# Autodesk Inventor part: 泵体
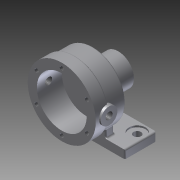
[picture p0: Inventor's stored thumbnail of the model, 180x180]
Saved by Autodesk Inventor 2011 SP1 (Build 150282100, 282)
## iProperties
Created: 2013-12
Part Number: 泵体
Document SubType Name: Modeling
Designer: Administrator
Density: 1 g/cm^3
Author: Administrator
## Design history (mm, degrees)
sketch "草图1"
  geometry: L1 (-48, 19)-(48, 19); L2 (48, 19)-(48, -19); L3 (48, -19)-(-48, -19); L4 (-48, -19)-(-48, 19); 3 further points
  constraints: 8 end point, 2 midpoint, 2 parallel, 1 horizontal, 1 horizontal alignment, 1 perpendicular, 1 vertical alignment
  dimensions: "d0" = 96 distance of L1.start L1.end; "d1" = 38 distance of L3.end L1.start
extrude "拉伸1" new body sketch "草图1" distance "d2" = 10; taper "d3" = 0 deg
node "工作平面1"
sketch "草图2"
  geometry: C1 r 41 at (48, 50); 1 further point
  constraints: 1 centre point
  dimensions: "d5" = 82 diameter of C1; "d6" = 50 distance of point (48, 0) C1.centre
extrude "拉伸2" join sketch "草图2" distance "d7" = 16; taper "d8" = 0 deg
sketch "草图3"
  geometry: C1 r 41 at (0, 0) reference; C2 r 39 at (0, 0); 1 further point
  constraints: 1 centre point, 1 coincident
  dimensions: "d9" = 78 diameter of C2
extrude "拉伸3" join sketch "草图3" distance "d10" = 22; taper "d11" = 0 deg
sketch "草图4"
  geometry: C1 r 39 at (0, 0) reference; C2 r 19 at (0, 0); 1 further point
  constraints: 1 centre point, 1 coincident
  dimensions: "d12" = 38 diameter of C2
extrude "拉伸4" join sketch "草图4" distance "d13" = 30; taper "d14" = 0 deg
sketch "草图5"
  geometry: L1 (48, -19)-(-48, -19) reference; L2 (-25, -19)-(25, -19); L3 (25, -19)-(25, -9); L4 (25, -9)-(-25, -9); L5 (-25, -9)-(-25, -19); 2 further points
  constraints: 8 end point, 2 midpoint, 2 parallel, 1 horizontal, 1 perpendicular
  dimensions: "d15" = 50 distance of L3.end L4.end; "d16" = 10 distance of L4.end L2.start
extrude "拉伸5" join sketch "草图5" stored distance "d17" = 40; taper "d18" = 0 deg
sketch "草图6"
  geometry: L1 (-9, 31)-(21, 31) reference; L2 (-19, 10)-(19, 10) reference; L3 (19, 10)-(14, 31); 1 further point
  constraints: 2 end point, 1 point on line
  dimensions: "d19" = 7 distance of L1.end L3.end
feature "加强筋1" sketch "草图6" dims "d20" = 1, "d21" = 10, "d22" = 0
hole "Hole1" diameter "d25" = 9; stored, may be unused: countersink angle "d29" = 90 deg, drill point angle "d31" = 118 deg; dims "d23" = 11, "d24" = 12, "d26" = 6, "d27" = 20, "d28" = 2, "d30" = 8
mirror "镜像1"
hole "Hole2" diameter "d34" = 22; stored, may be unused: countersink angle "d38" = 90 deg, drill point angle "d40" = 146 deg; dims "d32" = 10, "d33" = 10, "d35" = 6, "d36" = 4, "d37" = 2, "d39" = 5
hole "Hole3" diameter "d43" = 15; stored, may be unused: countersink angle "d47" = 90 deg, drill point angle "d49" = 0 deg; dims "d41" = 10, "d42" = 10, "d44" = 6, "d45" = 4, "d46" = 2, "d48" = 5
hole "Hole4" diameter "d52" = 60; stored, may be unused: countersink angle "d56" = 90 deg, drill point angle "d58" = 0 deg; dims "d50" = 10, "d51" = 10, "d53" = 6, "d54" = 4, "d55" = 2, "d57" = 30
chamfer "倒角1" distance "d59" = 1; stored, may be unused: second distance "d60" = 2, angle "d61" = 45 deg
sketch "草图7"
  geometry: C1 r 30 at (0, 0) reference; 2 further points
  dimensions: "d62" = 35 distance of C1.centre point (0, 35)
hole "Hole5" sketch "草图7" at (0, 35) diameter "d63" = 4.917; stored, may be unused: countersink angle "d67" = 90 deg, drill point angle "d69" = 120 deg; dims "d64" = 14, "d65" = 4, "d66" = 2, "d68" = 16
node "工作轴1"
pattern_circular "环形阵列1" dims angle "d71" = 360 deg
sketch "草图8"
  geometry: C1 r 11 at (0, 0) reference; 2 further points
  dimensions: "d73" = 15 distance of C1.centre point (0, 15)
hole "Hole6" sketch "草图8" at (0, 15) diameter "d74" = 3.242; stored, may be unused: countersink angle "d78" = 90 deg, drill point angle "d80" = 120 deg; dims "d75" = 10, "d76" = 4, "d77" = 2, "d79" = 12
pattern_circular "环形阵列2" dims angle "d82" = 360 deg
node "工作平面2"
sketch "草图9"
  geometry: L1 (-47, 9)-(-47, 91) reference; C1 r 10 at (-33, 50); 2 further points
  constraints: 1 centre point, 1 coincident
  dimensions: "d85" = 14 distance from line of L1 point (-33, 50); "d86" = 20 diameter of C1
extrude "拉伸6" join sketch "草图9" stored distance "d87" = 40; taper "d88" = 0 deg
mirror "镜像2"
hole "Hole7" diameter "d91" = 8.566; stored, may be unused: countersink angle "d95" = 90 deg, drill point angle "d97" = 120 deg; dims "d89" = 10, "d90" = 10, "d92" = 10, "d93" = 4, "d94" = 2, "d96" = 12
fillet "圆角1" dims "d98" = 2
fillet "圆角2" dims "d99" = 2
node "实体1"
node "工作轴2"
node "工作轴3"
other parameters: "d4" = 28, "d84" = 43
